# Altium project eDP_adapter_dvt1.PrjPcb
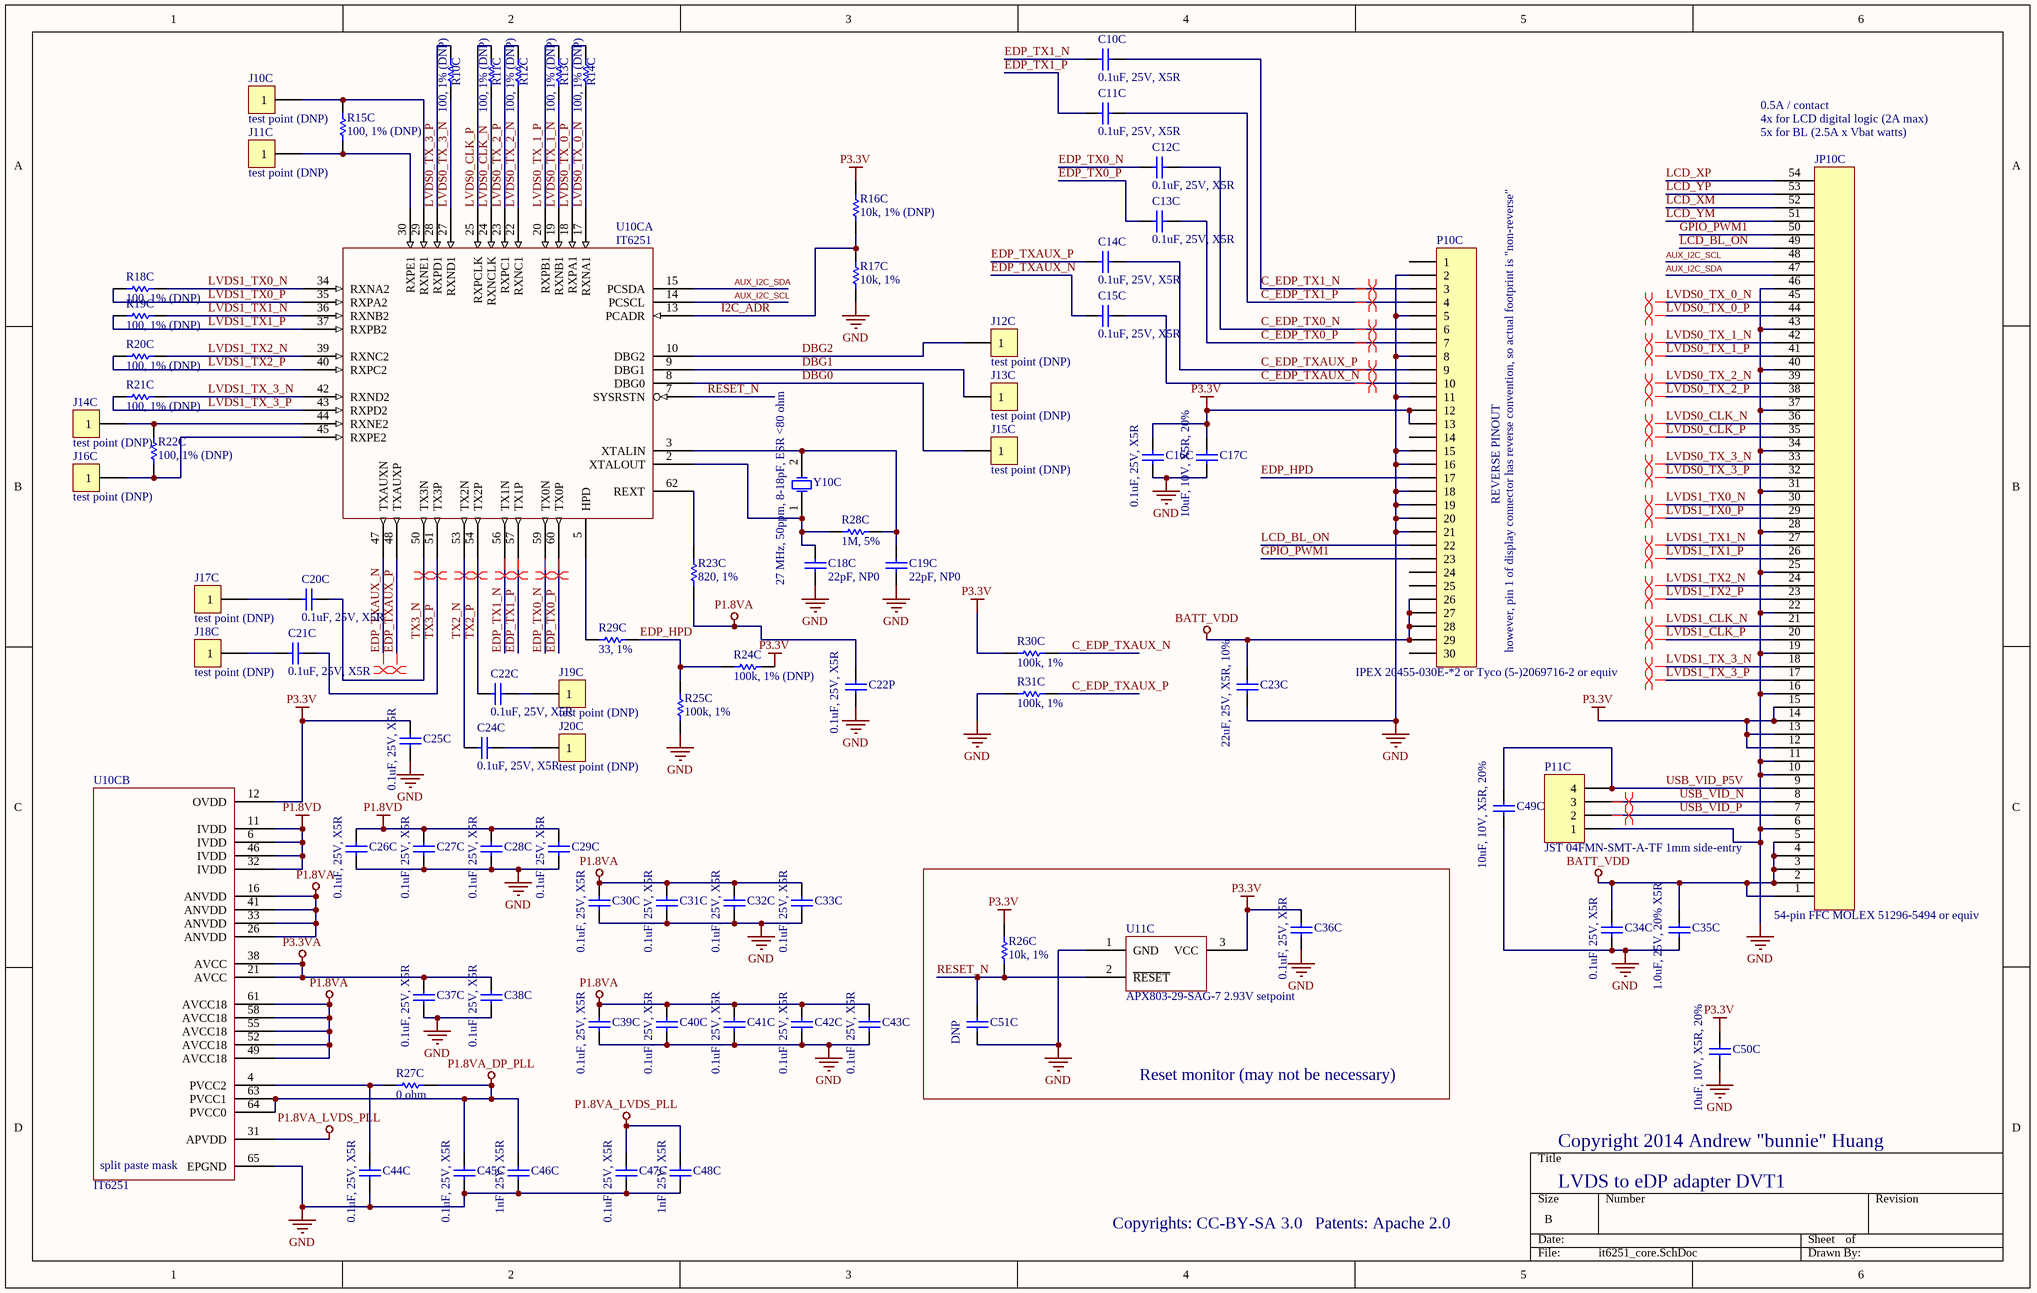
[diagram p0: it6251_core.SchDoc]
2 sheets, 112 parts. Net scope: global (net labels, ports and power ports of the same name join across sheets).
Board file: eDP_adapter_dvt1.PcbDoc
Sheets:
  it6251_core.SchDoc
  power.SchDoc

## Sheet it6251_core.SchDoc
size B

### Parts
C10C  0.1uF, 25V, X5R  [CAPC1005N]
C11C  0.1uF, 25V, X5R  [CAPC1005N]
C12C  0.1uF, 25V, X5R  [CAPC1005N]
C13C  0.1uF, 25V, X5R  [CAPC1005N]
C14C  0.1uF, 25V, X5R  [CAPC1005N]
C15C  0.1uF, 25V, X5R  [CAPC1005N]
C16C  0.1uF, 25V, X5R  [CAPC1005N]
C17C  10uF, 10V, X5R, 20%  [CAPC1608N]
C18C  22pF, NP0  [CAPC1005N]
C19C  22pF, NP0  [CAPC1005N]
C20C  0.1uF, 25V, X5R  [CAPC1005N]
C21C  0.1uF, 25V, X5R  [CAPC1005N]
C22C  0.1uF, 25V, X5R  [CAPC1005N]
C22P  0.1uF, 25V, X5R  [CAPC1005N]
C23C  22uF, 25V, X5R, 10%  [CAPC3225N]
C24C  0.1uF, 25V, X5R  [CAPC1005N]
C25C  0.1uF, 25V, X5R  [CAPC1005N]
C26C  0.1uF, 25V, X5R  [CAPC1005N]
C27C  0.1uF, 25V, X5R  [CAPC1005N]
C28C  0.1uF, 25V, X5R  [CAPC1005N]
C29C  0.1uF, 25V, X5R  [CAPC1005N]
C30C  0.1uF, 25V, X5R  [CAPC1005N]
C31C  0.1uF, 25V, X5R  [CAPC1005N]
C32C  0.1uF, 25V, X5R  [CAPC1005N]
C33C  0.1uF, 25V, X5R  [CAPC1005N]
C34C  0.1uF, 25V, X5R  [CAPC1005N]
C35C  1.0uF, 25V, 20% X5R  [CAPC1608N]
C36C  0.1uF, 25V, X5R  [CAPC1005N]
C37C  0.1uF, 25V, X5R  [CAPC1005N]
C38C  0.1uF, 25V, X5R  [CAPC1005N]
C39C  0.1uF, 25V, X5R  [CAPC1005N]
C40C  0.1uF, 25V, X5R  [CAPC1005N]
C41C  0.1uF, 25V, X5R  [CAPC1005N]
C42C  0.1uF, 25V, X5R  [CAPC1005N]
C43C  0.1uF, 25V, X5R  [CAPC1005N]
C44C  0.1uF, 25V, X5R  [CAPC1005N]
C45C  0.1uF, 25V, X5R  [CAPC1005N]
C46C  1nF, 25V, X5R  [CAPC1005N]
C47C  0.1uF, 25V, X5R  [CAPC1005N]
C48C  1nF, 25V, X5R  [CAPC1005N]
C49C  10uF, 10V, X5R, 20%  [CAPC1608N]
C50C  10uF, 10V, X5R, 20%  [CAPC1608N]
C51C  DNP  [CAPC1608N]
J10C  test point (DNP)  [TP_SMT_38mil]
J11C  test point (DNP)  [TP_SMT_38mil]
J12C  test point (DNP)  [TP_SMT_38mil]
J13C  test point (DNP)  [TP_SMT_38mil]
J14C  test point (DNP)  [TP_SMT_38mil]
J15C  test point (DNP)  [TP_SMT_38mil]
J16C  test point (DNP)  [TP_SMT_38mil]
J17C  test point (DNP)  [TP_SMT_38mil]
J18C  test point (DNP)  [TP_SMT_38mil]
J19C  test point (DNP)  [TP_SMT_38mil]
J20C  test point (DNP)  [TP_SMT_38mil]
JP10C  54-pin FFC MOLEX 51296-5494 or equiv  [MOLEX_51296_5494]
P10C  IPEX 20455-030E-*2 or Tyco (5-)2069716-2 or equiv  [TYCO_5-2069716-2]
P11C  JST 04FMN-SMT-A-TF 1mm side-entry  [JST_04FMN_SMT_A_TF]
R10C  100, 1% (DNP)  [RESC0603N]
R11C  100, 1% (DNP)  [RESC0603N]
R12C  100, 1% (DNP)  [RESC0603N]
R13C  100, 1% (DNP)  [RESC0603N]
R14C  100, 1% (DNP)  [RESC0603N]
R15C  100, 1% (DNP)  [RESC0603N]
R16C  10k, 1% (DNP)  [RESC1005N]
R17C  10k, 1%  [RESC1005N]
R18C  100, 1% (DNP)  [RESC0603N]
R19C  100, 1% (DNP)  [RESC0603N]
R20C  100, 1% (DNP)  [RESC0603N]
R21C  100, 1% (DNP)  [RESC0603N]
R22C  100, 1% (DNP)  [RESC0603N]
R23C  820, 1%  [RESC1005N]
R24C  100k, 1% (DNP)  [RESC1005N]
R25C  100k, 1%  [RESC1005N]
R26C  10k, 1%  [RESC1005N]
R27C  0 ohm  [RESC1005N]
R28C  1M, 5%  [RESC1005N]
R29C  33, 1%  [RESC1005N]
R30C  100k, 1%  [RESC1005N]
R31C  100k, 1%  [RESC1005N]
U10C  IT6251  [QFN50P900X900-64WAN]  (parts A,B of 2)
U11C  APX803-29-SAG-7 2.93V setpoint  [SOT23-3N]
Y10C  27 MHz, 50ppm, 8-18pF, ESR <80 ohm  [NDK_NX5032A]

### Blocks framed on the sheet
Reset monitor (may not be necessary): C36C C51C R26C U11C

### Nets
BATT_VDD: C23C.1 C34C.1 C35C.1 JP10C.1 JP10C.2 JP10C.3 JP10C.4 JP10C.5 P10C.26 P10C.27 P10C.28 P10C.29
GND: C16C.2 C17C.1 C18C.1 C19C.1 C22P.1 C23C.2 C25C.2 C26C.2 C27C.2 C28C.2 C29C.2 C30C.2 C31C.2 C32C.2 C33C.2 C34C.2 C35C.2 C36C.2 C37C.2 C38C.2 C39C.2 C40C.2 C41C.2 C42C.2 C43C.2 C44C.2 C45C.2 C46C.2 C47C.2 C48C.2 C49C.1 C50C.1 C51C.2 JP10C.6 JP10C.10 JP10C.11 JP10C.16 JP10C.19 JP10C.22 JP10C.25 JP10C.28 JP10C.31 JP10C.34 JP10C.37 JP10C.40 JP10C.43 JP10C.46 P10C.2 P10C.5 P10C.8 P10C.11 P10C.15 P10C.16 P10C.18 P10C.19 P10C.20 P10C.21 P11C.1 R17C.2 R25C.2 R31C.2 U10C.65(EPGND) U11C.1(GND)
P1.8VA: C22P.2 C30C.1 C31C.1 C32C.1 C33C.1 C39C.1 C40C.1 C41C.1 C42C.1 C43C.1 R23C.2 U10C.16(ANVDD) U10C.26(ANVDD) U10C.33(ANVDD) U10C.41(ANVDD) U10C.49(AVCC18) U10C.52(AVCC18) U10C.55(AVCC18) U10C.58(AVCC18) U10C.61(AVCC18)
P1.8VA_DP_PLL: C45C.1 C46C.1 R27C.1 U10C.63(PVCC1) U10C.64(PVCC0)
P1.8VA_LVDS_PLL: C47C.1 C48C.1 U10C.31(APVDD)
P1.8VD: C26C.1 C27C.1 C28C.1 C29C.1 U10C.6(IVDD) U10C.11(IVDD) U10C.32(IVDD) U10C.46(IVDD)
P3.3V: C16C.1 C17C.2 C25C.1 C36C.1 C50C.2 JP10C.12 JP10C.13 JP10C.14 JP10C.15 P10C.12 P10C.13 R16C.1 R24C.1 R26C.1 R30C.2 U10C.12(OVDD) U11C.3(VCC)
P3.3VA: C37C.1 C38C.1 U10C.21(AVCC) U10C.38(AVCC)
AUX_I2C_SCL: JP10C.48 U10C.14(PCSCL)
AUX_I2C_SDA: JP10C.47 U10C.15(PCSDA)
C_EDP_TX0_N: C12C.1 P10C.6
C_EDP_TX0_P: C13C.1 P10C.7
C_EDP_TX1_N: C10C.1 P10C.3
C_EDP_TX1_P: C11C.1 P10C.4
C_EDP_TXAUX_N: C15C.1 P10C.10 R30C.1
C_EDP_TXAUX_P: C14C.1 P10C.9 R31C.1
DBG0: J15C.1 U10C.8(DBG0)
DBG1: J13C.1 U10C.9(DBG1)
DBG2: J12C.1 U10C.10(DBG2)
EDP_HPD: P10C.17 R24C.2 R25C.1 R29C.2
EDP_TX0_N: C12C.2 U10C.59(TX0N)
EDP_TX0_P: C13C.2 U10C.60(TX0P)
EDP_TX1_N: C10C.2 U10C.56(TX1N)
EDP_TX1_P: C11C.2 U10C.57(TX1P)
EDP_TXAUX_N: C15C.2 U10C.47(TXAUXN)
EDP_TXAUX_P: C14C.2 U10C.48(TXAUXP)
GPIO_PWM1: JP10C.50 P10C.23
I2C_ADR: R16C.2 R17C.1 U10C.13(PCADR)
LCD_BL_ON: JP10C.49 P10C.22
LCD_XM: JP10C.52
LCD_XP: JP10C.54
LCD_YM: JP10C.51
LCD_YP: JP10C.53
LVDS0_CLK_N: JP10C.36 R11C.2 U10C.24(RXNCLK)
LVDS0_CLK_P: JP10C.35 R11C.1 U10C.25(RXPCLK)
LVDS0_TX_0_N: JP10C.45 R14C.2 U10C.17(RXNA1)
LVDS0_TX_0_P: JP10C.44 R14C.1 U10C.18(RXPA1)
LVDS0_TX_1_N: JP10C.42 R13C.2 U10C.19(RXNB1)
LVDS0_TX_1_P: JP10C.41 R13C.1 U10C.20(RXPB1)
LVDS0_TX_2_N: JP10C.39 R12C.2 U10C.22(RXNC1)
LVDS0_TX_2_P: JP10C.38 R12C.1 U10C.23(RXPC1)
LVDS0_TX_3_N: JP10C.33 R10C.2 U10C.27(RXND1)
LVDS0_TX_3_P: JP10C.32 R10C.1 U10C.28(RXPD1)
LVDS1_CLK_N: JP10C.21
LVDS1_CLK_P: JP10C.20
LVDS1_TX0_N: JP10C.30 R18C.1 U10C.34(RXNA2)
LVDS1_TX0_P: JP10C.29 R18C.2 U10C.35(RXPA2)
LVDS1_TX1_N: JP10C.27 R19C.1 U10C.36(RXNB2)
LVDS1_TX1_P: JP10C.26 R19C.2 U10C.37(RXPB2)
LVDS1_TX2_N: JP10C.24 R20C.1 U10C.39(RXNC2)
LVDS1_TX2_P: JP10C.23 R20C.2 U10C.40(RXPC2)
LVDS1_TX_3_N: JP10C.18 R21C.1 U10C.42(RXND2)
LVDS1_TX_3_P: JP10C.17 R21C.2 U10C.43(RXPD2)
RESET_N: C51C.1 R26C.2 U10C.7(SYSRSTN) U11C.2(~{RESET})
TX2_N: C24C.2 U10C.53(TX2N)
TX2_P: C22C.2 U10C.54(TX2P)
TX3_N: C20C.1 U10C.50(TX3N)
TX3_P: C21C.1 U10C.51(TX3P)
USB_VID_N: JP10C.8 P11C.3
USB_VID_P: JP10C.7 P11C.2
USB_VID_P5V: C49C.2 JP10C.9 P11C.4
NetC18C_2: C18C.2 R28C.2 U10C.2(XTALOUT) Y10C.1(OSC1)
NetC19C_2: C19C.2 R28C.1 U10C.3(XTALIN) Y10C.2(OSC2)
NetC20C_2: C20C.2 J17C.1
NetC21C_2: C21C.2 J18C.1
NetC22C_1: C22C.1 J19C.1
NetC24C_1: C24C.1 J20C.1
NetC44C_1: C44C.1 R27C.2 U10C.4(PVCC2)
NetJ10C_1: J10C.1 R15C.2 U10C.29(RXNE1)
NetJ11C_1: J11C.1 R15C.1 U10C.30(RXPE1)
NetJ14C_1: J14C.1 R22C.2 U10C.44(RXNE2)
NetJ16C_1: J16C.1 R22C.1 U10C.45(RXPE2)
NetR23C_1: R23C.1 U10C.62(REXT)
NetR29C_1: R29C.1 U10C.5(HPD)

Not connected (* = marked no-connect by the designer): P10C 1 14 24 25 30

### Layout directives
differential pair: C_EDP_TX0_N, C_EDP_TX0_P, C_EDP_TX1_N, C_EDP_TX1_P, C_EDP_TXAUX_N, C_EDP_TXAUX_P, EDP_TX0_N, EDP_TX0_P, EDP_TX1_N, EDP_TX1_P, EDP_TXAUX_N, EDP_TXAUX_P, LVDS0_CLK_N, LVDS0_CLK_P, LVDS0_TX_0_N, LVDS0_TX_0_P, LVDS0_TX_1_N, LVDS0_TX_1_P, LVDS0_TX_2_N, LVDS0_TX_2_P, LVDS0_TX_3_N, LVDS0_TX_3_P, LVDS1_CLK_N, LVDS1_CLK_P, LVDS1_TX0_N, LVDS1_TX0_P, LVDS1_TX1_N, LVDS1_TX1_P, LVDS1_TX2_N, LVDS1_TX2_P, LVDS1_TX_3_N, LVDS1_TX_3_P, TX2_N, TX2_P, TX3_N, TX3_P, USB_VID_N, USB_VID_P

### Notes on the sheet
- 0.5A / contact
- 4x for LCD digital logic (2A max)
- (near JP10C) 5x for BL (2.5A x Vbat watts)
- REVERSE PINOUT
- however, pin 1 of display connector has reverse convention, so actual footprint is "non-reverse"
- Copyright 2014 Andrew "bunnie" Huang
- Copyrights: CC-BY-SA 3.0
- Patents: Apache 2.0
- LVDS to eDP adapter DVT1

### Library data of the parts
C10C C11C C12C C13C C14C C15C C16C C17C C18C C19C C20C C21C C22C C22P C23C C24C C25C C26C C27C C28C C29C C30C C31C C32C C33C C34C C35C C36C C37C C38C C39C C40C C41C C42C C43C C44C C45C C46C C47C C48C C49C C50C C51C = Cap Semi: Capacitor (Semiconductor SIM Model)
J10C J11C J12C J13C J14C J15C J16C J17C J18C J19C J20C = CON1: Connector
JP10C = HEADER_54: Flat flex connector, 54 positions
P10C = Header 30
P11C = Header 4: Header, 4-Pin
R10C R11C R12C R13C R14C R15C R16C R17C R18C R19C R20C R21C R22C R23C R26C R27C R28C R29C = Res1: Resistor; Value: 100k
R24C R25C R30C R31C = Res1: Resistor
U10C = IT6251: LVDS to eDP converter
U11C = RESET_SOT23: Reset monitor. Voltage specified by XX in P/N. Multiple vendors.
Y10C = XTAL: Crystal Oscillator

## Sheet power.SchDoc
size A
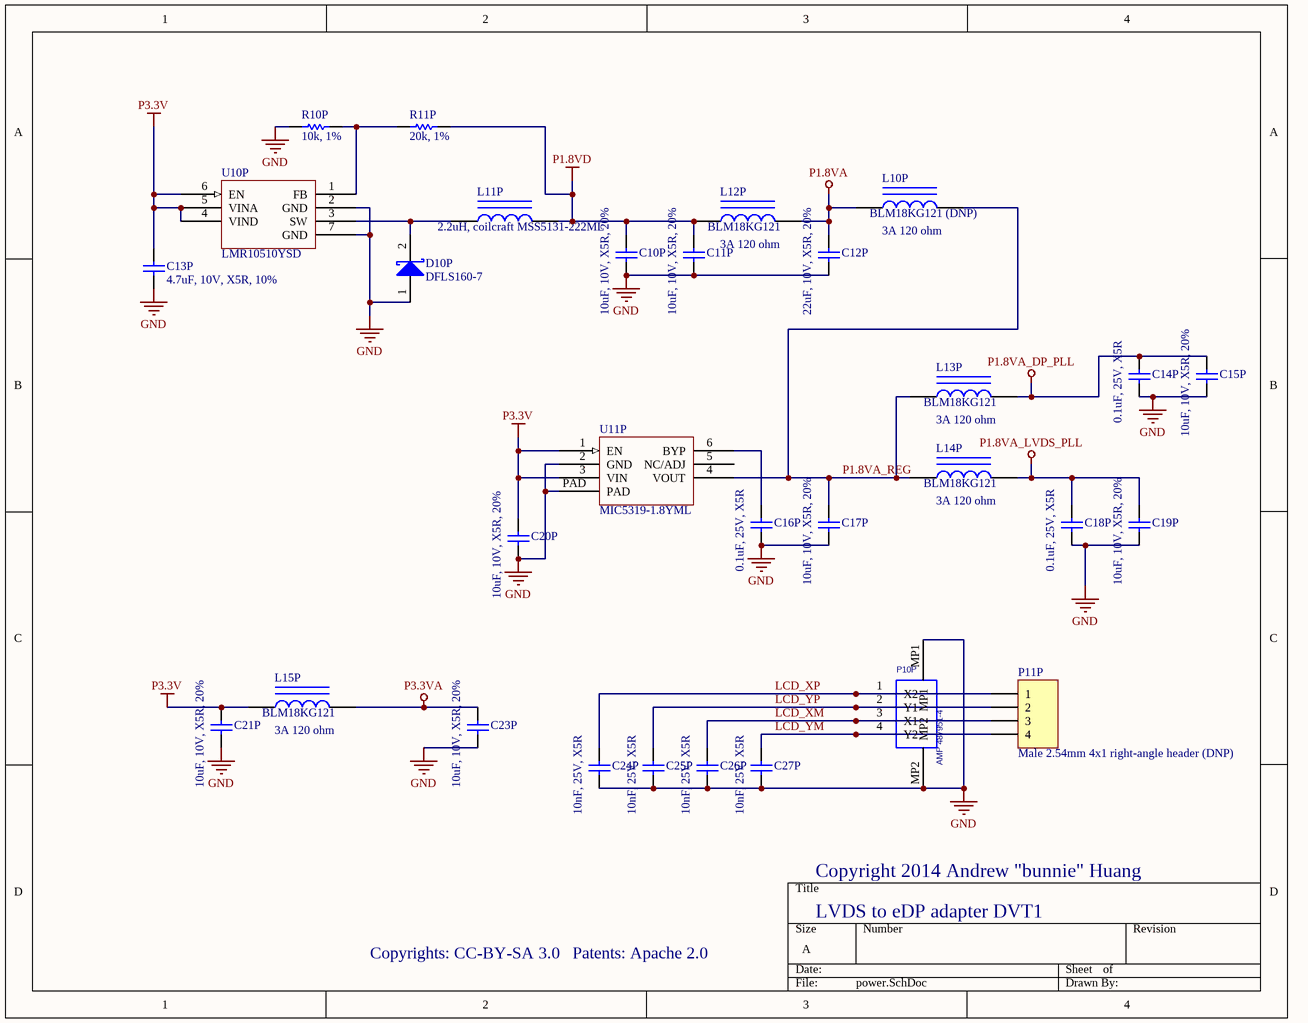
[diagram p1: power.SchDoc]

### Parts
C10P  10uF, 10V, X5R, 20%  [CAPC1608N]
C11P  10uF, 10V, X5R, 20%  [CAPC1608N]
C12P  22uF, 10V, X5R, 20%  [CAPC2012N]
C13P  4.7uF, 10V, X5R, 10%  [CAPC1608N]
C14P  0.1uF, 25V, X5R  [CAPC1005N]
C15P  10uF, 10V, X5R, 20%  [CAPC1608N]
C16P  0.1uF, 25V, X5R  [CAPC1005N]
C17P  10uF, 10V, X5R, 20%  [CAPC1608N]
C18P  0.1uF, 25V, X5R  [CAPC1005N]
C19P  10uF, 10V, X5R, 20%  [CAPC1608N]
C20P  10uF, 10V, X5R, 20%  [CAPC1608N]
C21P  10uF, 10V, X5R, 20%  [CAPC1608N]
C23P  10uF, 10V, X5R, 20%  [CAPC1608N]
C24P  10nF, 25V, X5R  [CAPC1005N]
C25P  10nF, 25V, X5R  [CAPC1005N]
C26P  10nF, 25V, X5R  [CAPC1005N]
C27P  10nF, 25V, X5R  [CAPC1005N]
D10P  DFLS160-7  [POWERDI-123]
L10P  BLM18KG121 (DNP)  value 3A 120 ohm  [INDC1608AN]
L11P  2.2uH, coilcraft MSS5131-222ML  [COILCRAFT_MSS5121]
L12P  BLM18KG121  value 3A 120 ohm  [INDC1608AN]
L13P  BLM18KG121  value 3A 120 ohm  [INDC1608AN]
L14P  BLM18KG121  value 3A 120 ohm  [INDC1608AN]
L15P  BLM18KG121  value 3A 120 ohm  [INDC1608AN]
P10P  AMP 487951-4  [AMP_487951_4]
P11P  Male 2.54mm 4x1 right-angle header (DNP)  [HDR1X4H]
R10P  10k, 1%  [RESC1005N]
R11P  20k, 1%  [RESC1005N]
U10P  LMR10510YSD  [SON95P300X300X80-7V]
U11P  MIC5319-1.8YML  [MICREL_MLF2x2_6]

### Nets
GND: C10P.1 C11P.1 C12P.2 C13P.2 C14P.1 C15P.1 C16P.1 C17P.1 C18P.1 C19P.1 C20P.1 C21P.1 C23P.1 C24P.1 C25P.1 C26P.1 C27P.1 D10P.1(A) P10P.MP1 P10P.MP2 R10P.2 U10P.2(GND) U10P.7(GND) U11P.2(GND) U11P.PAD
P1.8VA: C12P.1 L10P.1 L12P.2
P1.8VA_DP_PLL: C14P.2 C15P.2 L13P.2
P1.8VA_LVDS_PLL: C18P.2 C19P.2 L14P.2
P1.8VD: C10P.2 C11P.2 L11P.2 L12P.1 R11P.1
P3.3V: C13P.1 C20P.2 C21P.2 L15P.1 U10P.4(VIND) U10P.5(VINA) U10P.6(EN) U11P.1(EN) U11P.3(VIN)
P3.3VA: C23P.2 L15P.2
LCD_XM: C26P.2 P10P.3(X1) P11P.3
LCD_XP: C24P.2 P10P.1(X2) P11P.1
LCD_YM: C27P.2 P10P.4(Y2) P11P.4
LCD_YP: C25P.2 P10P.2(Y1) P11P.2
P1.8VA_REG: C17P.2 L10P.2 L13P.1 L14P.1 U11P.4(VOUT)
NetC16P_2: C16P.2 U11P.6(BYP)
NetD10P_2: D10P.2(K) L11P.1 U10P.3(SW)
NetR10P_1: R10P.1 R11P.2 U10P.1(FB)

Not connected (* = marked no-connect by the designer): U11P 5(NC/ADJ)

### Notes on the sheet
- Copyright 2014 Andrew "bunnie" Huang
- Copyrights: CC-BY-SA 3.0
- Patents: Apache 2.0
- LVDS to eDP adapter DVT1

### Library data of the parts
C10P C11P C12P C13P C14P C15P C16P C17P C18P C19P C20P C21P C23P C24P C25P C26P C27P = Cap Semi: Capacitor (Semiconductor SIM Model)
D10P = D Schottky: Schottky Diode; Code - JEDEC: DO-214-AA
L10P L11P L12P L13P L14P L15P = Inductor Iron: Magnetic-Core Inductor
P10P = TFT_TP_CON: Right: 30; Bottom: 50
P11P = Header 4H: Header, 4-Pin, Right Angle
R10P R11P = Res1: Resistor; Value: 100k
U10P = LMR10515XSD: NatSemi 1.5A step-down regulator in LLP
U11P = MIC5319-XXYML: 500 mA uCap ultra-low dropout high PSRR LDO regulator

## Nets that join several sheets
GND: it6251_core (63 pins), power (25 pins)
P1.8VA: it6251_core (20 pins), power (C12P.1 L10P.1 L12P.2)
P1.8VA_DP_PLL: it6251_core (5 pins), power (C14P.2 C15P.2 L13P.2)
P1.8VA_LVDS_PLL: it6251_core (C47C.1 C48C.1 U10C.31), power (C18P.2 C19P.2 L14P.2)
P1.8VD: it6251_core (8 pins), power (5 pins)
P3.3V: it6251_core (17 pins), power (9 pins)
P3.3VA: it6251_core (C37C.1 C38C.1 U10C.21 U10C.38), power (C23P.2 L15P.2)
LCD_XM: it6251_core (JP10C.52), power (C26P.2 P10P.3 P11P.3)
LCD_XP: it6251_core (JP10C.54), power (C24P.2 P10P.1 P11P.1)
LCD_YM: it6251_core (JP10C.51), power (C27P.2 P10P.4 P11P.4)
LCD_YP: it6251_core (JP10C.53), power (C25P.2 P10P.2 P11P.2)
